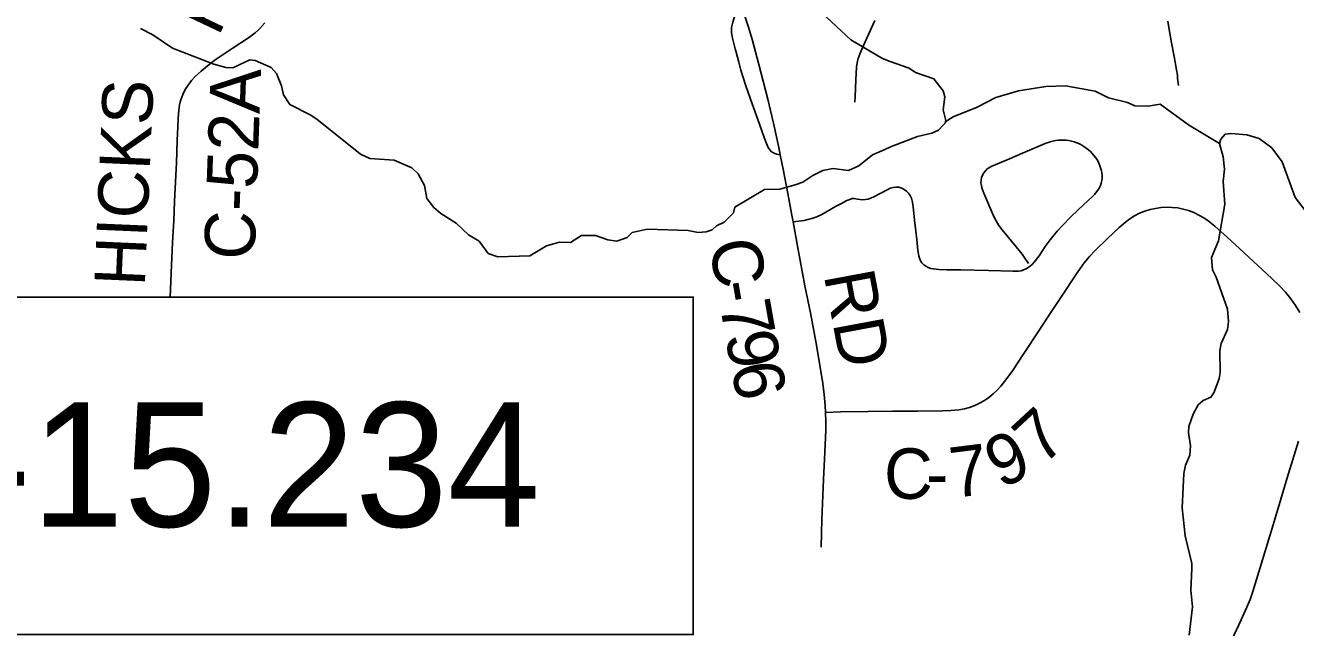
# Model space of a CAD drawing. Extents: x 0 to 34, y 0 to 22.
# Drawn here: x 5.879 to 7.308, y 15.827 to 16.504 of the extents above; entities that cross this region are included whole.
import ezdxf

# ---------------------------------------------------------------- set-up
doc = ezdxf.new("R2010")
doc.units = 0
for name, color, linetype in [('Default', 7, 'Continuous'), ('GM_X_County_Road', 7, 'Continuous'), ('GM_X_County_Road_Text', 7, 'Continuous'), ('GM_X_Minor_River', 7, 'Continuous'), ('GM_X_Township_Road', 7, 'Continuous')]:
    doc.layers.add(name, color=color, linetype=linetype)

msp = doc.modelspace()

# ---------------------------------------------------------------- linework, layer by layer
at = {"layer": 'Default'}
msp.add_lwpolyline([(5.112, 16.1987), (6.6303, 16.1987), (6.6303, 15.8189), (5.112, 15.8189)], close=True, dxfattribs=at)
at = {"layer": 'GM_X_County_Road'}
for points in [[(6.7282, 16.3586), (6.7265, 16.3668), (6.7205, 16.3942), (6.7141, 16.4214), (6.704, 16.4605), (6.6968, 16.4875), (6.6924, 16.5024), (6.6836, 16.5295)], [(6.0418, 16.1987), (6.0421, 16.2072), (6.0428, 16.2259), (6.0444, 16.2599), (6.0456, 16.2848), (6.0466, 16.3065), (6.0486, 16.3499), (6.0496, 16.3748), (6.0502, 16.3902), (6.0506, 16.3995), (6.0513, 16.4088), (6.0521, 16.4149), (6.0528, 16.4179), (6.0536, 16.4208), (6.0557, 16.4266), (6.0584, 16.4321), (6.0617, 16.4373), (6.0655, 16.4422), (6.0697, 16.4467), (6.0764, 16.453), (6.0836, 16.4588), (6.0935, 16.4663), (6.1012, 16.4716), (6.1115, 16.4784), (6.1297, 16.4903), (6.1373, 16.4959), (6.1412, 16.4992), (6.1425, 16.5007), (6.148, 16.5074)], [(6.7426, 16.2834), (6.7413, 16.2907), (6.7367, 16.3151), (6.7313, 16.3425), (6.7282, 16.3586)], [(6.779, 16.0688), (6.7959, 16.0695), (6.827, 16.0699), (6.8549, 16.0701), (6.8829, 16.0703), (6.9108, 16.0705), (6.9201, 16.0709), (6.9293, 16.0718), (6.9354, 16.0729), (6.9413, 16.0744), (6.947, 16.0765), (6.9526, 16.0791), (6.9579, 16.0822), (6.9629, 16.0857), (6.9677, 16.0896), (6.9722, 16.0938), (6.9764, 16.0983), (6.9822, 16.1055), (6.9894, 16.1155), (7.0031, 16.1362), (7.0185, 16.1596), (7.0304, 16.1778), (7.0425, 16.1959), (7.063, 16.227), (7.0703, 16.2371), (7.0762, 16.2443), (7.0825, 16.2512), (7.0959, 16.2642), (7.1095, 16.277), (7.1166, 16.2831), (7.1216, 16.2868), (7.127, 16.2901), (7.1326, 16.2929), (7.1384, 16.2952), (7.1444, 16.2971), (7.1506, 16.2984), (7.1568, 16.2993), (7.1631, 16.2997), (7.1694, 16.2996), (7.1756, 16.2989), (7.1818, 16.2977), (7.1878, 16.2959), (7.1937, 16.2937), (7.1993, 16.291), (7.2048, 16.2878), (7.2099, 16.2843), (7.2172, 16.2784), (7.2312, 16.266), (7.2449, 16.2533), (7.2814, 16.2196), (7.2903, 16.211), (7.2968, 16.2041), (7.3027, 16.1968), (7.3081, 16.1892), (7.3129, 16.1812)], [(6.779, 16.0688), (6.7786, 16.0768), (6.7777, 16.0892), (6.7761, 16.1015), (6.7688, 16.1444), (6.7621, 16.181), (6.756, 16.2115), (6.7479, 16.2541), (6.7426, 16.2834)], [(6.7741, 15.9174), (6.7748, 15.9482), (6.777, 15.9934), (6.778, 16.0163), (6.7793, 16.0487), (6.7794, 16.0581), (6.779, 16.0688)], [(7.3114, 16.0367), (7.2988, 15.9951), (7.2916, 15.9713), (7.2816, 15.9386), (7.26, 15.8672), (7.2569, 15.8583), (7.2534, 15.8497), (7.2468, 15.8356), (7.2415, 15.8243), (7.2365, 15.813), (7.2321, 15.8014), (7.2272, 15.7867), (7.2191, 15.76), (7.2128, 15.7391)]]:
    msp.add_lwpolyline(points, dxfattribs=at)
at = {"layer": 'GM_X_Minor_River'}
for points in [[(6.9139, 16.3946), (6.9147, 16.3972), (6.9116, 16.4093), (6.9134, 16.4241), (6.9115, 16.4309), (6.9012, 16.4442), (6.8804, 16.4513), (6.8732, 16.4562), (6.8519, 16.4637), (6.8432, 16.467), (6.8076, 16.4881), (6.7692, 16.5239)], [(6.1313, 16.4655), (6.1121, 16.4566), (6.1041, 16.457), (6.0909, 16.4607), (6.0442, 16.4786), (6.0222, 16.4937), (6.0082, 16.5009)], [(7.3314, 16.2798), (7.3078, 16.3108), (7.2932, 16.351), (7.2814, 16.3665), (7.267, 16.377), (7.2533, 16.3812), (7.2355, 16.3826), (7.2287, 16.3818), (7.2239, 16.3764), (7.2224, 16.3715), (7.1943, 16.3884), (7.1875, 16.3926), (7.1559, 16.4156), (7.1423, 16.4136), (7.1272, 16.4139), (7.1189, 16.4176), (7.0977, 16.4228), (7.0825, 16.4303), (7.0492, 16.4362), (7.0272, 16.4357), (6.9962, 16.4306), (6.9709, 16.4233), (6.9498, 16.4122), (6.9226, 16.4014), (6.9166, 16.3976), (6.9064, 16.3865), (6.8989, 16.383), (6.8826, 16.3795), (6.8524, 16.3676), (6.8453, 16.3645), (6.832, 16.3588), (6.8166, 16.3462), (6.8049, 16.3412), (6.7875, 16.3433), (6.7761, 16.341), (6.7648, 16.3356), (6.7535, 16.328), (6.746, 16.3253), (6.7278, 16.3202), (6.7104, 16.3198), (6.6772, 16.2998), (6.6754, 16.2934), (6.6652, 16.2831), (6.6565, 16.2788), (6.6517, 16.2743), (6.6449, 16.272), (6.6358, 16.2715), (6.6244, 16.2737), (6.5783, 16.275), (6.5616, 16.2715), (6.556, 16.2658), (6.5443, 16.2615), (6.5341, 16.263), (6.5204, 16.2679), (6.5045, 16.2678), (6.4921, 16.2601), (6.4796, 16.2604), (6.4653, 16.2562), (6.4464, 16.2451), (6.4105, 16.2441), (6.3995, 16.2478), (6.3892, 16.2615), (6.3774, 16.2686), (6.3634, 16.2818), (6.3463, 16.2927), (6.3383, 16.2995), (6.3303, 16.3097), (6.328, 16.3242), (6.3207, 16.3374), (6.3135, 16.3442), (6.2938, 16.3528), (6.2665, 16.3546), (6.2559, 16.3594), (6.2066, 16.3987), (6.199, 16.4036), (6.1762, 16.4152), (6.1693, 16.4262), (6.167, 16.4364), (6.1613, 16.4504), (6.1552, 16.4569), (6.1374, 16.4647), (6.1313, 16.4655)], [(7.2224, 16.3715), (7.2266, 16.3563), (7.2282, 16.3427), (7.2267, 16.3286), (7.2284, 16.3032), (7.2214, 16.2618), (7.2136, 16.2431), (7.2148, 16.2295), (7.2186, 16.2211), (7.2316, 16.1851), (7.2328, 16.1711), (7.2314, 16.162), (7.2243, 16.1464), (7.2228, 16.1384), (7.2233, 16.1137), (7.2222, 16.1069), (7.2203, 16.1019), (7.2162, 16.0909), (7.2128, 16.0859), (7.2042, 16.0821), (7.1985, 16.0775), (7.1929, 16.0668), (7.188, 16.0531), (7.1877, 16.0459), (7.19, 16.0311), (7.1893, 16.0209), (7.1841, 16.0095), (7.1822, 16.0003), (7.1806, 15.9616), (7.1837, 15.9301), (7.1915, 15.899), (7.1915, 15.8929), (7.1901, 15.869), (7.1921, 15.85), (7.1885, 15.8181)]]:
    msp.add_lwpolyline(points, dxfattribs=at)
at = {"layer": 'GM_X_Township_Road'}
for points in [[(6.6785, 16.4742), (6.6775, 16.478), (6.6746, 16.49), (6.6734, 16.496), (6.6732, 16.4991), (6.6734, 16.5021), (6.6749, 16.5081), (6.6792, 16.5228), (6.6802, 16.5251), (6.6816, 16.5274), (6.6836, 16.5295)], [(6.8122, 16.4179), (6.8126, 16.4241), (6.8133, 16.4427), (6.8141, 16.4582), (6.815, 16.4643), (6.8159, 16.4673), (6.818, 16.4731), (6.8218, 16.4817), (6.8256, 16.4901), (6.8345, 16.5099)], [(7.1763, 16.4367), (7.1754, 16.4451), (7.1751, 16.4482), (7.1742, 16.4543), (7.1713, 16.4694), (7.1683, 16.4846), (7.1657, 16.4999), (7.1644, 16.5091)], [(6.7282, 16.3586), (6.724, 16.3594), (6.7212, 16.3606), (6.7185, 16.3622), (6.7163, 16.3644), (6.7146, 16.3669), (6.7133, 16.3696), (6.7099, 16.3781), (6.7028, 16.3985), (6.6967, 16.416), (6.6896, 16.4365), (6.6838, 16.4541), (6.6814, 16.463), (6.6785, 16.4742)], [(6.7426, 16.2834), (6.7551, 16.285), (6.7607, 16.2862), (6.7637, 16.2869), (6.7694, 16.289), (6.7749, 16.2916), (6.7905, 16.3004), (6.7973, 16.3041), (6.8032, 16.3072), (6.8064, 16.3086), (6.809, 16.3094), (6.8113, 16.3095), (6.8152, 16.3087), (6.8212, 16.3081), (6.8241, 16.3083), (6.8271, 16.3089), (6.8299, 16.3098), (6.8327, 16.311), (6.8491, 16.3199), (6.852, 16.3212), (6.8552, 16.3221), (6.8584, 16.3224), (6.8617, 16.3222), (6.8649, 16.3213), (6.8678, 16.3199), (6.8704, 16.3179), (6.8727, 16.3155), (6.8744, 16.3128), (6.8758, 16.3099), (6.8767, 16.3068), (6.8778, 16.3006), (6.8794, 16.2852), (6.8809, 16.2728), (6.882, 16.2635), (6.883, 16.2512), (6.884, 16.2452), (6.8849, 16.2423), (6.8861, 16.2396), (6.8877, 16.2372), (6.8897, 16.235), (6.892, 16.2333), (6.8947, 16.232), (6.8975, 16.231), (6.9005, 16.2304), (6.9065, 16.2298), (6.9158, 16.2294), (6.9313, 16.2292), (6.9625, 16.2284), (6.9901, 16.2278), (6.9963, 16.228), (6.9993, 16.2283), (7.002, 16.2293), (7.0049, 16.2306), (7.0077, 16.2322), (7.0095, 16.2335), (7.0119, 16.2358), (7.0139, 16.238), (7.0196, 16.2451), (7.0265, 16.2555), (7.0321, 16.263), (7.0399, 16.2727), (7.0462, 16.2797), (7.0549, 16.2886), (7.0639, 16.2972), (7.0797, 16.3119), (7.0818, 16.3141), (7.0856, 16.3189), (7.0872, 16.3214), (7.0884, 16.3241), (7.0894, 16.3269), (7.09, 16.3298), (7.0903, 16.3328), (7.0903, 16.3358), (7.09, 16.3388), (7.0894, 16.3417), (7.0874, 16.3475), (7.0863, 16.3503), (7.0848, 16.353), (7.0832, 16.3555), (7.0793, 16.3602), (7.0772, 16.3624), (7.0749, 16.3645), (7.07, 16.3681), (7.0674, 16.3697), (7.0648, 16.3712), (7.062, 16.3724), (7.0591, 16.3733), (7.0531, 16.3747), (7.0501, 16.3751), (7.0471, 16.3754), (7.044, 16.3754), (7.041, 16.3752), (7.038, 16.3748), (7.035, 16.3742), (7.0321, 16.3734), (7.0264, 16.3713), (7.0035, 16.3618), (6.9835, 16.3532), (6.9663, 16.346), (6.9636, 16.3446), (6.9612, 16.3429), (6.9591, 16.3409), (6.9573, 16.3385), (6.9558, 16.3359), (6.9547, 16.3332), (6.9542, 16.3303), (6.9541, 16.3273), (6.9545, 16.3244), (6.9552, 16.3215), (6.9573, 16.3157), (6.9682, 16.2899), (6.971, 16.2845), (6.9742, 16.2793), (6.9779, 16.2743), (6.9938, 16.2553), (7.0005, 16.2468), (7.0028, 16.2436), (7.0076, 16.2366)]]:
    msp.add_lwpolyline(points, dxfattribs=at)

# ---------------------------------------------------------------- texts
at = {"layer": 'Default'}
msp.add_text('MUS-70-15.234', height=0.14, dxfattribs=at).set_placement((5.1364, 15.9402))
at = {"layer": 'GM_X_County_Road_Text'}
for s, height, rotation, p in [('R', 0.0568, 64.6377, (6.0958, 16.4909)), ('C-52A', 0.05682, 87.999, (6.1365, 16.2399)), ('HICKS', 0.05682, 87.5293, (6.013, 16.2102)), ('C', 0.0568, 280.0109, (6.6477, 16.2598)), ('RD', 0.05682, 280.5603, (6.777, 16.2237)), ('-', 0.0568, 280.0288, (6.6558, 16.2138)), ('7', 0.0568, 280.0728, (6.6599, 16.1908)), ('9', 0.0568, 280.2992, (6.666, 16.1561)), ('6', 0.0568, 281.1061, (6.6724, 16.1208)), ('7', 0.0568, 42.7259, (7.0234, 16.0078)), ('9', 0.0568, 25.3431, (6.9763, 15.9823)), ('C', 0.0568, 0.0664, (6.845, 15.9716)), ('7', 0.0568, 7.1199, (6.9227, 15.9725)), ('-', 0.0568, 0.8154, (6.8925, 15.9717))]:
    msp.add_text(s, height=height, rotation=rotation, dxfattribs=at).set_placement(p)

doc.saveas('drawing.dxf')
